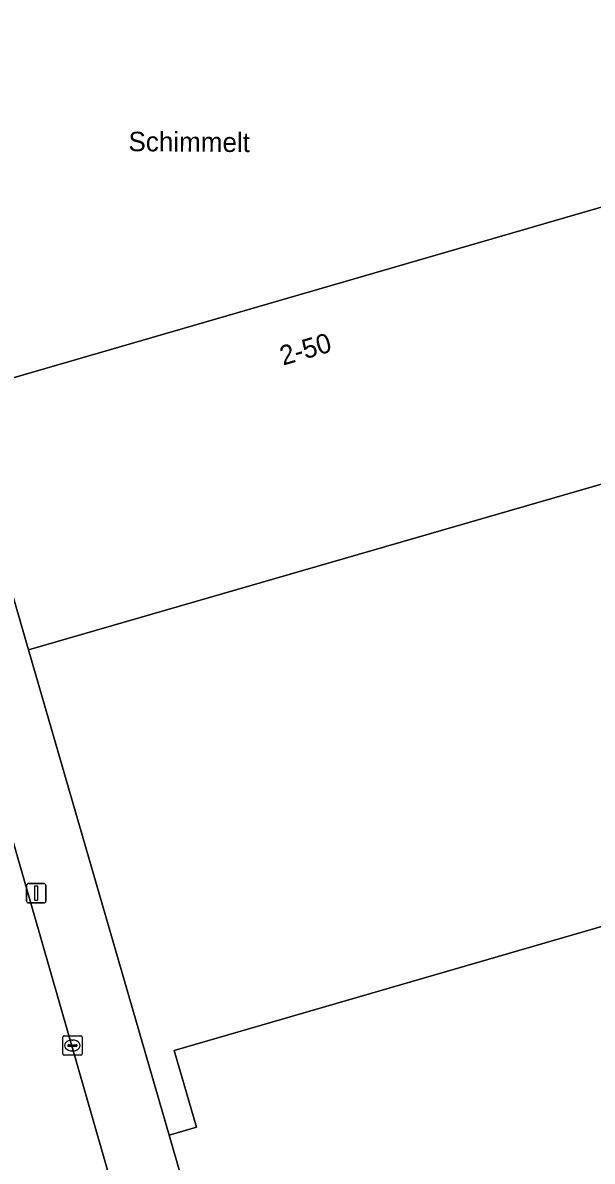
# Model space of a CAD drawing. Extents: x 160806 to 161707, y 383696 to 384148.
# Drawn here: x 161113.6 to 161142.9, y 383725.3 to 383783.8 of the extents above; entities that cross this region are included whole.
import ezdxf

# ---------------------------------------------------------------- set-up
doc = ezdxf.new("R2010")
doc.units = 0
for name, color, linetype in [('IMGEO_Fietspad_open', 7, 'Continuous'), ('IMGEO_Kolk', 7, 'Continuous'), ('IMGEO_Lichtmast', 7, 'Continuous'), ('IMGEO_Muur', 7, 'Continuous'), ('IMGEO_Openbare_ruimte_label', 7, 'Continuous'), ('IMGEO_Pand', 7, 'Continuous'), ('IMGEO_Pand_nummerreeks', 7, 'Continuous'), ('IMGEO_Pand_overbouw', 7, 'Continuous'), ('IMGEO_Parkeervlak_gesloten', 7, 'Continuous'), ('IMGEO_Parkeervlak_open', 7, 'Continuous'), ('IMGEO_Voetpad_open', 7, 'Continuous')]:
    doc.layers.add(name, color=color, linetype=linetype)

msp = doc.modelspace()

# ---------------------------------------------------------------- linework, layer by layer
at = {"layer": 'IMGEO_Fietspad_open'}
msp.add_lwpolyline([(161123.777, 383706.403), (161123.276, 383707.694), (161123.236, 383707.812), (161122.975, 383708.589), (161122.859, 383708.842), (161122.656, 383709.073), (161122.247, 383709.896), (161112.327, 383744.363), (161110.707, 383750), (161094.816, 383804.968)], dxfattribs=at)
at = {"layer": 'IMGEO_Kolk'}
for p, q in [((161115.659, 383730.787), (161115.659, 383731.639)), ((161115.734, 383731.713), (161116.586, 383731.713)), ((161115.918, 383731.207), (161115.918, 383731.219)), ((161115.961, 383731.256), (161116.359, 383731.256)), ((161116.147, 383731.493), (161116.172, 383731.493)), ((161116.402, 383731.219), (161116.402, 383731.207)), ((161116.66, 383731.639), (161116.66, 383730.787)), ((161116.586, 383730.713), (161115.734, 383730.713)), ((161116.356, 383731.17), (161115.958, 383731.17)), ((161116.17, 383730.933), (161116.145, 383730.933))]:
    msp.add_line(p, q, dxfattribs=at)
for points in [[(161115.659, 383730.787), (161115.659, 383731.639)], [(161115.734, 383731.713), (161116.586, 383731.713)], [(161116.66, 383731.639), (161116.66, 383730.787)], [(161116.586, 383730.713), (161115.734, 383730.713)]]:
    msp.add_lwpolyline(points, dxfattribs=at)
for centre, radius, start, end in [((161115.736, 383731.637), 0.0765, 91.55205, 178.44795), ((161115.736, 383731.637), 0.0765, 91.55205, 178.44795), ((161115.958, 383731.216), 0.0403, 85.87752, 175.75265), ((161115.955, 383731.206), 0.0366, 178.93798, 274.71019), ((161116.359, 383731.213), 0.043, 264.86636, 352.45326), ((161116.363, 383731.218), 0.0386, 1.73085, 96.63898), ((161116.584, 383731.637), 0.0765, 1.55205, 88.44795), ((161116.584, 383731.637), 0.0765, 1.55205, 88.44795), ((161115.736, 383730.789), 0.0765, 181.55205, 268.44795), ((161115.736, 383730.789), 0.0765, 181.55205, 268.44795), ((161116.584, 383730.789), 0.0765, 271.55205, 358.44795), ((161116.584, 383730.789), 0.0765, 271.55205, 358.44795)]:
    msp.add_arc(centre, radius, start, end, dxfattribs=at)
for centre, major_axis, ratio, start_param, end_param in [((161116.146, 383731.213), (-0.387, 0.002), 0.722429, 4.712389, 7.853982), ((161116.171, 383731.213), (-0.39, 0.002), 0.717154, 1.570796, 4.712389)]:
    msp.add_ellipse(centre, major_axis=major_axis, ratio=ratio, start_param=start_param, end_param=end_param, dxfattribs=at)
at = {"layer": 'IMGEO_Lichtmast'}
for p, q in [((161113.803, 383738.64), (161113.803, 383739.44)), ((161113.803, 383739.44), (161113.803, 383738.64)), ((161113.903, 383739.54), (161114.693, 383739.54)), ((161114.693, 383739.54), (161113.903, 383739.54)), ((161114.793, 383739.44), (161114.793, 383738.64)), ((161114.793, 383738.64), (161114.793, 383739.44)), ((161114.693, 383738.54), (161113.903, 383738.54)), ((161113.903, 383738.54), (161114.693, 383738.54))]:
    msp.add_line(p, q, dxfattribs=at)
msp.add_lwpolyline([(161114.223, 383739.415), (161114.373, 383739.415), (161114.373, 383738.665), (161114.223, 383738.665), (161114.223, 383739.415)], dxfattribs=at)
for centre, start, end in [((161113.903, 383739.44), 90, 180), ((161113.903, 383739.44), 90, 180), ((161114.693, 383739.44), 0, 90), ((161114.693, 383739.44), 360, 90), ((161113.903, 383738.64), 180, 270), ((161113.903, 383738.64), 180, 270), ((161114.693, 383738.64), 270, 0), ((161114.693, 383738.64), 270, 0)]:
    msp.add_arc(centre, 0.1, start, end, dxfattribs=at)
at = {"layer": 'IMGEO_Muur'}
msp.add_lwpolyline([(161113.902, 383751.548), (161121.123, 383726.602)], dxfattribs=at)
at = {"layer": 'IMGEO_Pand'}
for points in [[(161144.737, 383774.709), (161111.5, 383765.061), (161112.655, 383761.086), (161111.258, 383760.68), (161113.902, 383751.548), (161148.546, 383761.579)], [(161155.994, 383734.659), (161157.669, 383735.142), (161158.189, 383735.292), (161157.546, 383735.978), (161155.286, 383738.389), (161154.664, 383740.617), (161121.382, 383730.964), (161122.53, 383727.008), (161121.123, 383726.602), (161123.797, 383717.365), (161158.428, 383727.402), (161158.225, 383728.109), (161157.885, 383728.008)]]:
    msp.add_lwpolyline(points, close=True, dxfattribs=at)
at = {"layer": 'IMGEO_Pand_overbouw'}
msp.add_lwpolyline([(161244.397, 383752.352), (161218.72, 383841.978), (161097.833, 383806.973), (161123.797, 383717.365)], close=True, dxfattribs=at)
at = {"layer": 'IMGEO_Parkeervlak_gesloten'}
msp.add_lwpolyline([(161113.902, 383751.548), (161121.123, 383726.602), (161122.53, 383727.008), (161121.382, 383730.964), (161154.664, 383740.617), (161161.241, 383742.441), (161159.142, 383749.659), (161159.059, 383750), (161158.79, 383751.101), (161159.91, 383751.416), (161160.45, 383751.574), (161159.336, 383755.412), (161158.801, 383755.259), (161157.692, 383754.928), (161157.212, 383756.317), (161155.146, 383763.443), (161148.546, 383761.579)], close=True, dxfattribs=at)
at = {"layer": 'IMGEO_Parkeervlak_open'}
msp.add_lwpolyline([(161104.037, 383785.627), (161111.258, 383760.68), (161112.655, 383761.086), (161111.5, 383765.061), (161144.737, 383774.709), (161151.34, 383776.574), (161149.261, 383783.747), (161149.393, 383783.784), (161148.975, 383785.247), (161150.034, 383785.528), (161150.572, 383785.685), (161149.449, 383789.537), (161148.91, 383789.383), (161147.854, 383789.064), (161147.448, 383790.495), (161147.304, 383790.45), (161145.248, 383797.544), (161138.655, 383795.672)], close=True, dxfattribs=at)
at = {"layer": 'IMGEO_Voetpad_open'}
for points in [[(161113.902, 383751.548), (161111.258, 383760.68), (161104.037, 383785.627), (161098.648, 383804.243), (161097.833, 383806.973), (161100.524, 383807.822), (161109.952, 383810.749), (161117.397, 383812.973), (161128.047, 383816.337), (161128.761, 383816.562), (161140.029, 383820.121), (161140.252, 383820.19), (161145.264, 383821.735)], [(161094.816, 383804.968), (161110.707, 383750), (161112.327, 383744.363), (161122.247, 383709.896), (161122.656, 383709.073), (161122.859, 383708.842), (161122.975, 383708.589)], [(161123.392, 383709.156), (161124.109, 383709.233), (161125.699, 383709.405), (161126.009, 383709.438), (161123.797, 383717.365), (161121.123, 383726.602), (161113.902, 383751.548)]]:
    msp.add_lwpolyline(points, dxfattribs=at)

# ---------------------------------------------------------------- texts
at = {"layer": 'IMGEO_Openbare_ruimte_label'}
msp.add_text('Schimmelt', height=1, rotation=359.54164, dxfattribs=at).set_placement((161119.034, 383777.181))
at = {"layer": 'IMGEO_Pand_nummerreeks'}
msp.add_text('2-50', height=1, rotation=16.1966, dxfattribs=at).set_placement((161126.977, 383766.155))

doc.saveas('drawing.dxf')
